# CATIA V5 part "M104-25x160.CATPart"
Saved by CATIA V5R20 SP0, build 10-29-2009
Part number: M104-25x160
Source: Unknown
Bounding box of the stored display mesh (mm): x -12.497 to 12.497, y -12.358 to 12.358, z 0 to 160
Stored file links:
  C:\Users\Utente\Desktop\IO LAVORO\3D X SITO CF\X SITO\M104\M104-25x160.CATPart
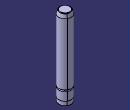
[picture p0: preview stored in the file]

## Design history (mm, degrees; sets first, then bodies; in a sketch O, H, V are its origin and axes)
Body1 (main body)
  Solid1 "PartBody": solid without history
